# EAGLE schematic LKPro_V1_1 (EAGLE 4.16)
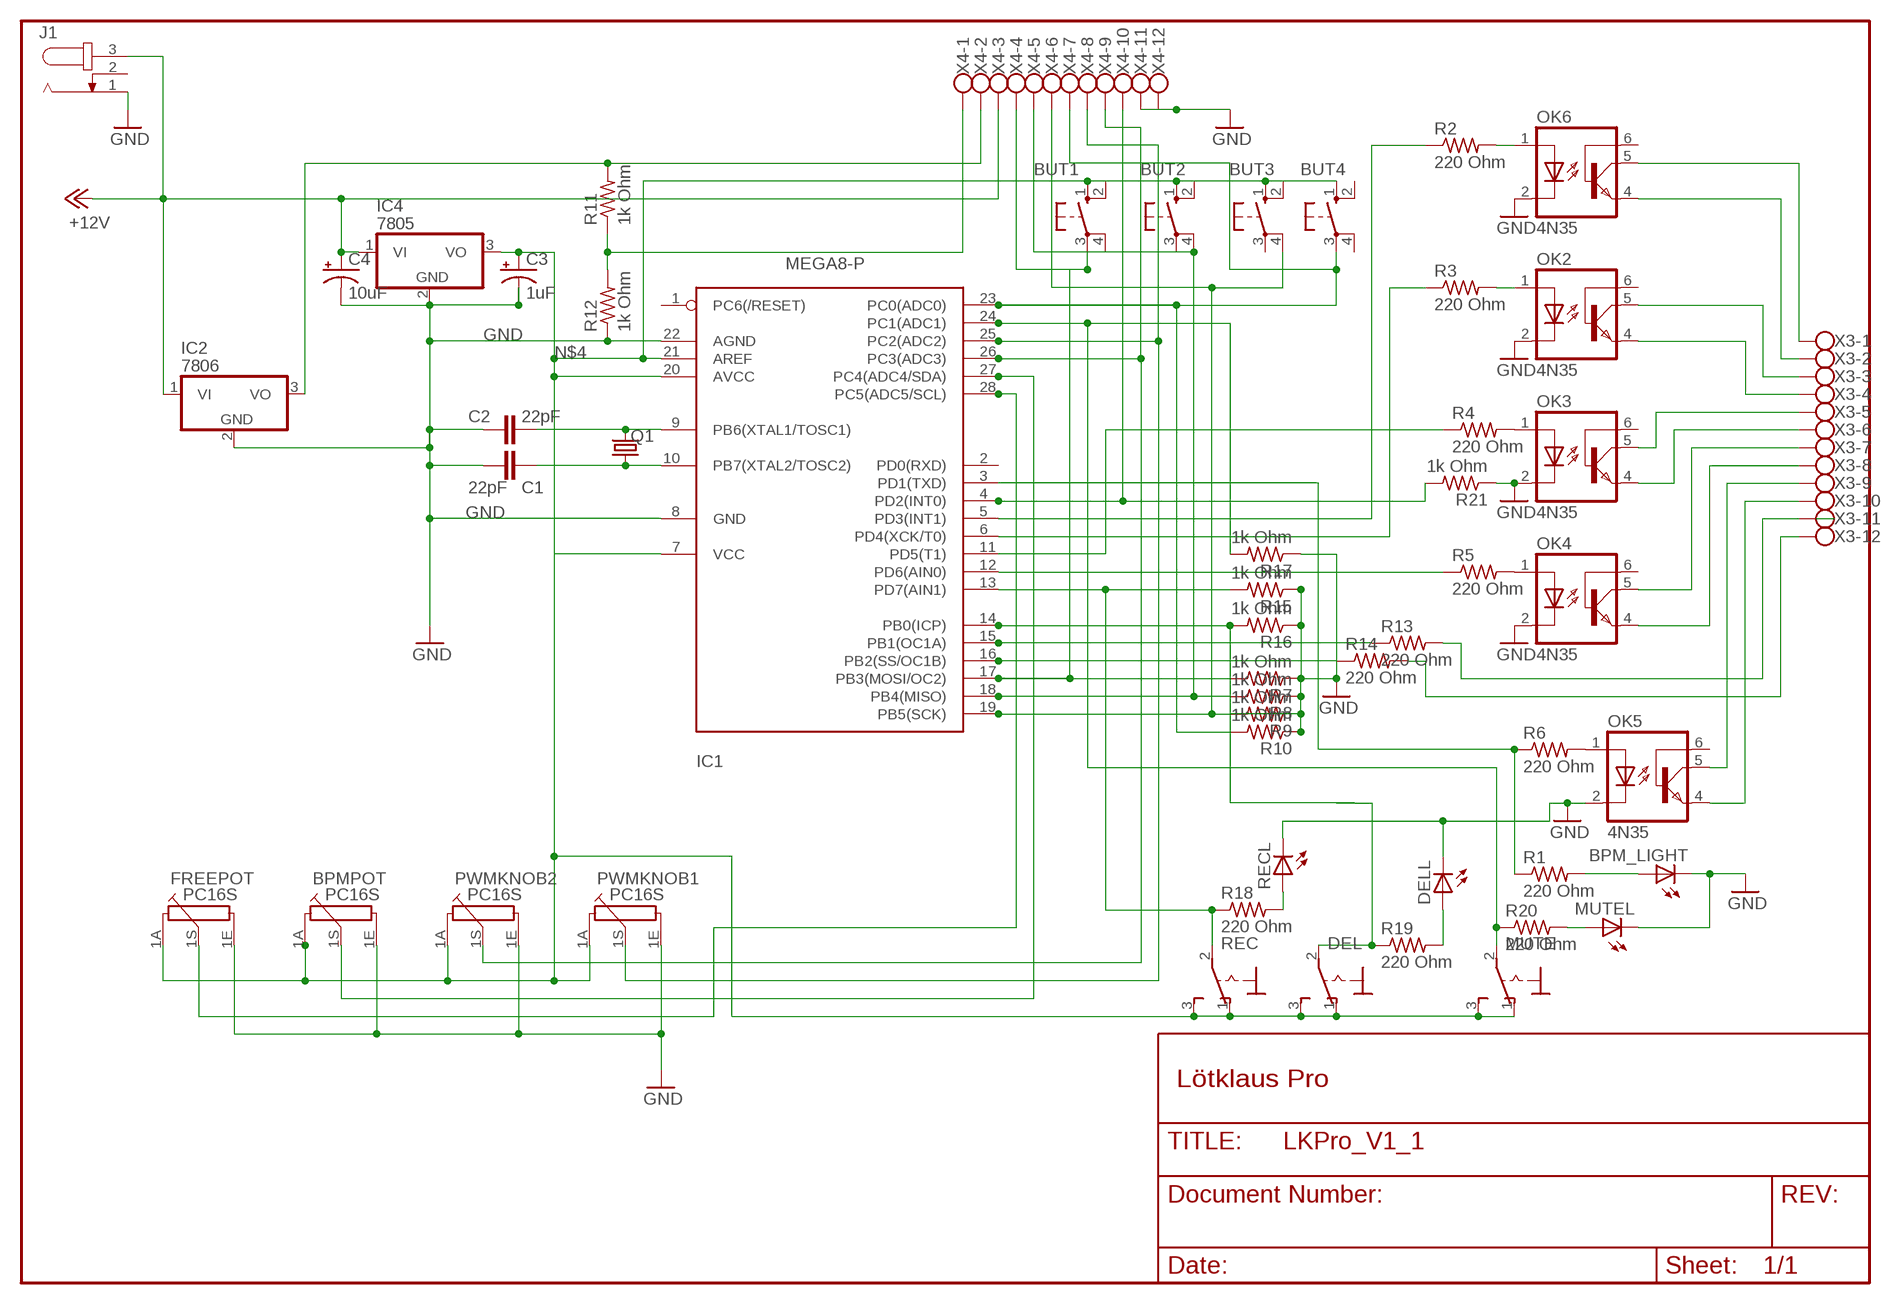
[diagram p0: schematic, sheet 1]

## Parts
BPM_LIGHT  LED5MM  [LED5MM]
BPMPOT  PC16S  [PC16S]
BUT1  10-XX  [B3F-10XX]
BUT2  10-XX  [B3F-10XX]
BUT3  10-XX  [B3F-10XX]
BUT4  10-XX  [B3F-10XX]
C1  22pF  C-EU025-024X044  [C025-024X044]
C2  22pF  C-EU025-024X044  [C025-024X044]
C3  1uF  CPOL-USE2,5-6E  [E2,5-6E]
C4  10uF  CPOL-USE2,5-6E  [E2,5-6E]
DEL  320-916  [320-916]
DELL  LED3MM  [LED3MM]
FREEPOT  PC16S  [PC16S]
IC1  MEGA8-P  [DIL28-3]
IC2  7806  78  [TO220V]
IC4  7805  78  [TO220V]
J1  JACK-PLUG0  [SPC4077]
MUTE  320-916  [320-916]
MUTEL  LED3MM  [LED3MM]
OK2  4N35  [DIL06]
OK3  4N35  [DIL06]
OK4  4N35  [DIL06]
OK5  4N35  [DIL06]
OK6  4N35  [DIL06]
PWMKNOB1  PC16S  [PC16S]
PWMKNOB2  PC16S  [PC16S]
Q1  CRYSTALHC49U70  [HC49U70]
R1  220 Ohm  R-US_0204/7  [0204/7]
R2  220 Ohm  R-US_0204/7  [0204/7]
R3  220 Ohm  R-US_0204/7  [0204/7]
R4  220 Ohm  R-US_0204/7  [0204/7]
R5  220 Ohm  R-US_0204/7  [0204/7]
R6  220 Ohm  R-US_0204/7  [0204/7]
R7  1k Ohm  R-US_0204/7  [0204/7]
R8  1k Ohm  R-US_0204/7  [0204/7]
R9  1k Ohm  R-US_0204/7  [0204/7]
R10  1k Ohm  R-US_0204/7  [0204/7]
R11  1k Ohm  R-US_0204/7  [0204/7]
R12  1k Ohm  R-US_0204/7  [0204/7]
R13  220 Ohm  R-US_0204/7  [0204/7]
R14  220 Ohm  R-US_0204/7  [0204/7]
R15  1k Ohm  R-US_0204/7  [0204/7]
R16  1k Ohm  R-US_0204/7  [0204/7]
R17  1k Ohm  R-US_0204/7  [0204/7]
R18  220 Ohm  R-US_0204/7  [0204/7]
R19  220 Ohm  R-US_0204/7  [0204/7]
R20  220 Ohm  R-US_0204/7  [0204/7]
R21  1k Ohm  R-US_0204/7  [0204/7]
REC  320-916  [320-916]
RECL  LED3MM  [LED3MM]
X3  W237-12P  [W237-12P]
X4  W237-12P  [W237-12P]

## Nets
+12V: C4.+ IC2.1(VI) IC4.1(VI) J1.3 X4.3
GND: BPM_LIGHT.K(C) BPMPOT.1E C1.2 C2.2 C3.- C4.- DELL.K(C) FREEPOT.1E IC1.8(GND) IC1.22(AGND) IC2.2(GND) IC4.2(GND) J1.1 MUTEL.K(C) OK2.2(C) OK3.2(C) OK4.2(C) OK5.2(C) OK6.2(C) PWMKNOB1.1E PWMKNOB2.1E R7.1 R8.1 R9.1 R10.1 R12.1 R15.1 R16.1 R17.1 R21.1 RECL.K(C) X4.11 X4.12
N$1: C2.1 IC1.9(PB6(XTAL1/TOSC1)) Q1.2
N$2: C1.1 IC1.10(PB7(XTAL2/TOSC2)) Q1.1
N$3: OK6.1(A) R2.2
N$4: BPMPOT.1A BUT1.1(S) BUT2.1(S) BUT3.1(S) BUT4.1(S) C3.+ DEL.1(O) DEL.3(S) FREEPOT.1A IC1.7(VCC) IC1.20(AVCC) IC1.21(AREF) IC4.3(VO) MUTE.1(O) MUTE.3(S) PWMKNOB1.1A PWMKNOB2.1A REC.1(O) REC.3(S)
N$5: OK6.5(COL) X3.1
N$6: IC1.3(PD1(TXD)) R1.1 R6.1
N$7: BPM_LIGHT.A R1.2
N$8: OK2.1(A) R3.2
N$9: OK3.1(A) R4.2
N$10: OK4.1(A) R5.2
N$11: OK5.1(A) R6.2
N$12: OK6.4(EMI) X3.2
N$13: OK2.5(COL) X3.3
N$14: OK2.4(EMI) X3.4
N$15: OK3.5(COL) X3.5
N$16: OK3.4(EMI) X3.6
N$17: OK4.5(COL) X3.7
N$18: OK4.4(EMI) X3.8
N$19: OK5.5(COL) X3.9
N$20: OK5.4(EMI) X3.10
N$21: IC2.3(VO) R11.2 X4.2
N$22: R11.1 R12.2 X4.1
N$23: DEL.2(P) IC1.14(PB0(ICP)) R16.2 R19.1
N$24: IC1.5(PD3(INT1)) R2.1
N$25: IC1.6(PD4(XCK/T0)) R3.1
N$26: IC1.11(PD5(T1)) R4.1
N$27: IC1.12(PD6(AIN0)) R5.1
N$28: BUT1.3(P) IC1.17(PB3(MOSI/OC2)) R7.2 X4.4
N$29: BUT2.3(P) BUT2.4(P1) IC1.18(PB4(MISO)) R8.2 X4.5
N$30: BUT3.4(P1) IC1.19(PB5(SCK)) R9.2 X4.6
N$31: BUT4.3(P) IC1.23(PC0(ADC0)) R10.2 X4.7
N$32: IC1.16(PB2(SS/OC1B)) R14.1
N$33: IC1.15(PB1(OC1A)) R13.1
N$34: R13.2 X3.11
N$35: R14.2 X3.12
N$37: IC1.25(PC2(ADC2)) PWMKNOB1.1S X4.8
N$38: IC1.26(PC3(ADC3)) PWMKNOB2.1S X4.9
N$39: BPMPOT.1S IC1.27(PC4(ADC4/SDA))
N$40: R18.2 RECL.A
N$41: IC1.13(PD7(AIN1)) R15.2 R18.1 REC.2(P)
N$42: IC1.24(PC1(ADC1)) MUTE.2(P) R17.2 R20.1
N$43: FREEPOT.1S IC1.28(PC5(ADC5/SCL))
N$44: MUTEL.A R20.2
N$45: DELL.A R19.2
N$47: IC1.4(PD2(INT0)) R21.2 X4.10
Unconnected: BUT1.2(S1) BUT1.4(P1) BUT2.2(S1) BUT3.2(S1) BUT3.3(P) BUT4.2(S1) BUT4.4(P1) IC1.1(PC6(/RESET)) IC1.2(PD0(RXD)) J1.2 OK2.6(BAS) OK3.6(BAS) OK4.6(BAS) OK5.6(BAS) OK6.6(BAS)

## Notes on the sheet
- Lötklaus Pro

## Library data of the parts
BPM_LIGHT DELL MUTEL RECL = led:LED: LED
BPMPOT FREEPOT PWMKNOB1 PWMKNOB2 = piher:PC16S: POTENTIOMETER single carbon potentiometer, 16 mm, S3ROH
BUT1-BUT4 = switch-omron:10-XX: OMRON SWITCH
C1 C2 = rcl:C-EU: CAPACITOR, European symbol
C3 C4 = rcl:CPOL-US: POLARIZED CAPACITOR, American symbol
DEL MUTE REC = switch:320-916: TOGGLE SWITCH distributor RS Components
IC1 = atmel:MEGA8-P: MICROCONTROLLER 8 Kbytes FLASH 1 kbytes SRAM 512 bytes EEPROM USART 4-channel 10 bit ADC 2-channel 8 bit ADC Source: avr.lbr
IC2 IC4 = linear:78*: Positive VOLTAGE REGULATOR Source: http://cache.national.com/ds/LM/LM78L05.pdf http://www.fairchildsemi.com/ds/LM/LM7805.pdf
J1 = con-jack:JACK-PLUG: DC POWER JACK Power Jack, DC, Right Angle, Through Hole, Rated 5A at 16VDC, PC Terminals Distributor: Farnell (www.Farnell.de) Drawing: 84N1161.pdf / 84N1162.pdf Manufacturer: SPC Technology (www.spctechnology.com) Type: SPC4077 / SPC 4078
OK2-OK6 = optocoupler:4N35: MOTOROLA OPTO COUPLER
Q1 = crystal:CRYSTAL: CRYSTAL
R1-R21 = rcl:R-US_: RESISTOR, American symbol
X3 X4 = con-wago-508:W237-12P: WAGO SREW CLAMP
